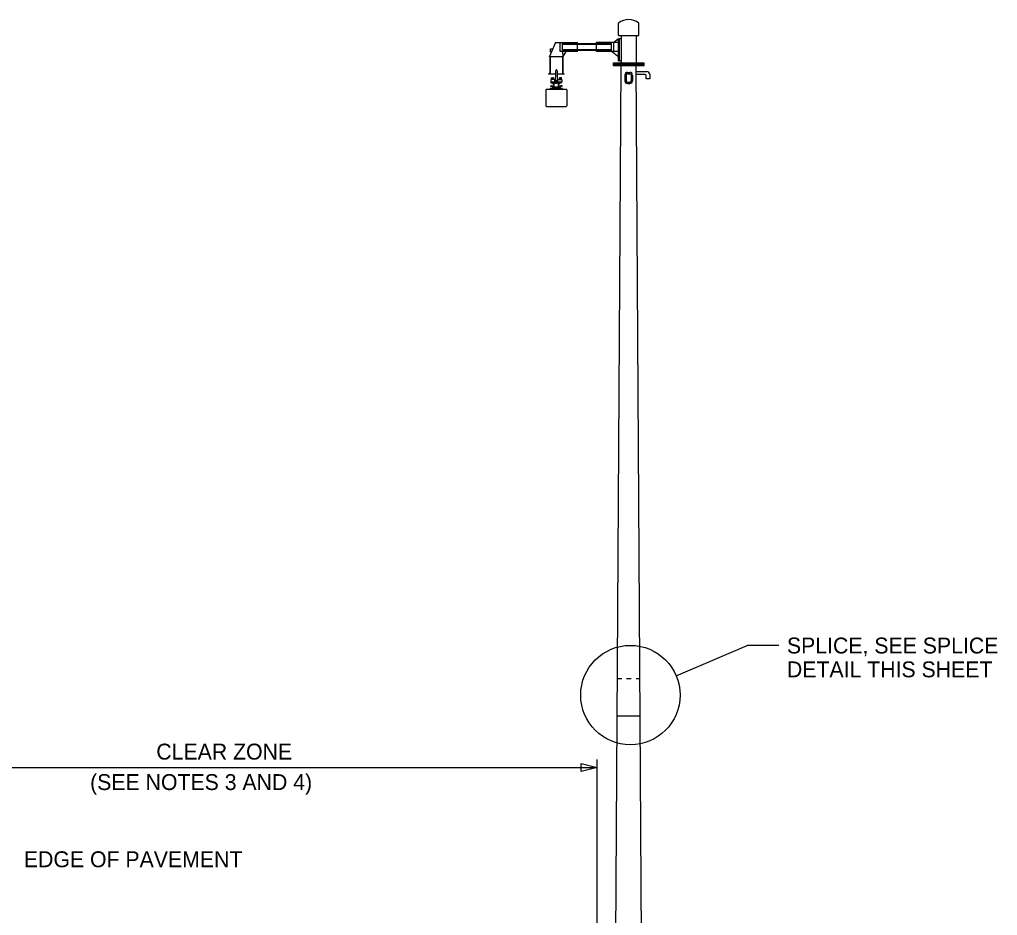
# Model space of a CAD drawing. Extents: x 1299104.8 to 1299141.6, y 239639.8 to 239661.8.
# Drawn here: x 1299111.4 to 1299118.78, y 239647.52 to 239654.28 of the extents above; entities that cross this region are included whole.
import ezdxf

# ---------------------------------------------------------------- set-up
doc = ezdxf.new("R2010")
doc.units = 0
for name, color, linetype in [('0-STEEL POLE', 7, 'Continuous'), ('DIM TXT', 7, 'Continuous'), ('Level 3', 7, 'Continuous'), ('Level 8', 7, 'Continuous')]:
    doc.layers.add(name, color=color, linetype=linetype)

# ---------------------------------------------------------------- blocks, each defined once
blk = doc.blocks.new('_U22')
at = {"layer": '0-STEEL POLE'}
for p, q in [((-0.054, 0.042), (-0.054, -0.042)), ((-0.035, 0.042), (-0.035, -0.042)), ((-0.018, 0.078), (0.018, 0.078)), ((-0.018, 0.06), (0.018, 0.06)), ((0.036, 0.042), (0.036, -0.042)), ((0.054, 0.041), (0.054, -0.042)), ((-0.018, -0.06), (0.018, -0.06)), ((-0.018, -0.077), (0.018, -0.077))]:
    blk.add_line(p, q, dxfattribs=at)
for centre, radius, start, end in [((-0.018, 0.042), 0.0357, 89.9999, 179.9999), ((-0.018, 0.042), 0.0179, 89.9999, 179.9999), ((0.018, 0.042), 0.0357, 359.9999, 89.9999), ((0.018, 0.042), 0.0179, 359.9999, 89.9999), ((-0.018, -0.042), 0.0357, 179.9999, 269.9999), ((-0.018, -0.042), 0.0179, 179.9999, 269.9999), ((0.018, -0.042), 0.0179, 269.9999, 359.9999), ((0.018, -0.042), 0.0357, 269.9999, 359.9999)]:
    blk.add_arc(centre, radius, start, end, dxfattribs=at)

msp = doc.modelspace()

# ---------------------------------------------------------------- linework, layer by layer
at = {"layer": 'Level 3'}
for p, q in [((1299115.9199, 239654.1559), (1299115.9199, 239654.2498)), ((1299116.0735, 239654.1559), (1299116.0735, 239654.2498)), ((1299115.4444, 239654.1034), (1299115.398, 239653.9986)), ((1299115.4444, 239654.1034), (1299115.6104, 239654.1034)), ((1299115.4805, 239654.036), (1299115.4805, 239654.1034)), ((1299115.4971, 239654.036), (1299115.4971, 239654.1034)), ((1299115.4971, 239654.095), (1299115.6104, 239654.095)), ((1299115.6104, 239654.095), (1299115.6104, 239654.1034)), ((1299115.6104, 239654.036), (1299115.6104, 239654.095)), ((1299115.6104, 239654.095), (1299115.7528, 239654.095)), ((1299115.9189, 239654.1034), (1299115.7528, 239654.1034)), ((1299115.7528, 239654.036), (1299115.7528, 239654.1034)), ((1299115.7528, 239654.095), (1299115.8661, 239654.095)), ((1299115.8661, 239654.036), (1299115.8661, 239654.1034)), ((1299115.9189, 239654.1314), (1299115.8845, 239654.1034)), ((1299115.8845, 239654.036), (1299115.8845, 239654.1034)), ((1299115.9189, 239653.9654), (1299115.9189, 239654.1314)), ((1299115.9189, 239654.1314), (1299115.9276, 239654.1314)), ((1299115.9199, 239654.1559), (1299116.0735, 239654.1559)), ((1299115.9276, 239653.9654), (1299115.9276, 239654.1314)), ((1299115.9399, 239654.1314), (1299115.9276, 239654.1314)), ((1299115.9399, 239654.1559), (1299115.9399, 239653.9498)), ((1299116.0535, 239654.1559), (1299116.0535, 239653.9498)), ((1299115.4063, 239654.0332), (1299115.4063, 239654.0563)), ((1299115.4063, 239654.0332), (1299115.4133, 239654.0332)), ((1299115.4065, 239654.0562), (1299115.4235, 239654.0562)), ((1299115.6104, 239654.036), (1299115.4805, 239654.036)), ((1299115.4971, 239654.0904), (1299115.6104, 239654.0904)), ((1299115.4971, 239654.0508), (1299115.6104, 239654.0508)), ((1299115.4971, 239654.0462), (1299115.6104, 239654.0462)), ((1299115.5024, 239653.9986), (1299115.5, 239654.036)), ((1299115.5024, 239653.9986), (1299115.5248, 239654.036)), ((1299115.5259, 239654.0462), (1299115.5361, 239654.0462)), ((1299115.5822, 239654.0462), (1299115.5923, 239654.0462)), ((1299115.6104, 239654.0904), (1299115.7528, 239654.0904)), ((1299115.6104, 239654.0508), (1299115.7528, 239654.0508)), ((1299115.6104, 239654.0462), (1299115.7528, 239654.0462)), ((1299115.7528, 239654.0904), (1299115.8661, 239654.0904)), ((1299115.7528, 239654.0508), (1299115.8661, 239654.0508)), ((1299115.7528, 239654.0462), (1299115.8661, 239654.0462)), ((1299115.8661, 239654.036), (1299115.7528, 239654.036)), ((1299115.7709, 239654.036), (1299115.7528, 239654.036)), ((1299115.7709, 239654.0462), (1299115.7811, 239654.0462)), ((1299115.8272, 239654.0462), (1299115.8373, 239654.0462)), ((1299115.9189, 239654.036), (1299115.8373, 239654.036)), ((1299115.9189, 239653.9945), (1299115.8661, 239654.036)), ((1299115.398, 239653.9986), (1299115.5024, 239653.9986)), ((1299115.398, 239653.9945), (1299115.398, 239653.9986)), ((1299115.5024, 239653.9945), (1299115.398, 239653.9945)), ((1299115.398, 239653.9945), (1299115.3998, 239653.9945)), ((1299115.4035, 239653.9966), (1299115.3998, 239653.9966)), ((1299115.3998, 239653.9945), (1299115.3998, 239653.9966)), ((1299115.402, 239653.9945), (1299115.402, 239653.8755)), ((1299115.4984, 239653.9945), (1299115.402, 239653.9945)), ((1299115.4028, 239653.9945), (1299115.4028, 239653.8745)), ((1299115.4035, 239653.9945), (1299115.4035, 239653.9966)), ((1299115.4969, 239653.9966), (1299115.5006, 239653.9966)), ((1299115.4969, 239653.9945), (1299115.4969, 239653.9966)), ((1299115.4976, 239653.9945), (1299115.4976, 239653.8745)), ((1299115.4984, 239653.9945), (1299115.4984, 239653.8755)), ((1299115.5006, 239653.9945), (1299115.5006, 239653.9966)), ((1299115.5006, 239653.9945), (1299115.5024, 239653.9945)), ((1299115.5024, 239653.9945), (1299115.5024, 239653.9986)), ((1299115.9189, 239653.9654), (1299115.9276, 239653.9654)), ((1299115.9399, 239653.9654), (1299115.9276, 239653.9654)), ((1299115.4439, 239653.8819), (1299115.4424, 239653.8032)), ((1299115.4468, 239653.8959), (1299115.4439, 239653.8819)), ((1299115.4477, 239653.8967), (1299115.4527, 239653.8967)), ((1299115.4536, 239653.8959), (1299115.4565, 239653.8819)), ((1299115.4565, 239653.8819), (1299115.4575, 239653.8032)), ((1299115.883, 239644.3884), (1299115.9399, 239653.9384)), ((1299116.1104, 239644.3884), (1299116.0535, 239653.9384)), ((1299115.3909, 239653.8663), (1299115.3909, 239653.8653)), ((1299115.4436, 239653.8653), (1299115.3909, 239653.8653)), ((1299115.4081, 239653.8233), (1299115.4081, 239653.8051)), ((1299115.4368, 239653.8251), (1299115.4099, 239653.8251)), ((1299115.4099, 239653.8033), (1299115.4203, 239653.8032)), ((1299115.4124, 239653.7972), (1299115.4124, 239653.8032)), ((1299115.4166, 239653.8032), (1299115.4124, 239653.8032)), ((1299115.4132, 239653.8251), (1299115.4132, 239653.827)), ((1299115.4141, 239653.8279), (1299115.4141, 239653.8363)), ((1299115.416, 239653.8279), (1299115.4141, 239653.8279)), ((1299115.416, 239653.8279), (1299115.416, 239653.8363)), ((1299115.4169, 239653.8251), (1299115.4169, 239653.827)), ((1299115.4175, 239653.8251), (1299115.4175, 239653.827)), ((1299115.4575, 239653.8032), (1299115.4175, 239653.8032)), ((1299115.4185, 239653.8279), (1299115.4185, 239653.8363)), ((1299115.4203, 239653.8279), (1299115.4185, 239653.8279)), ((1299115.4203, 239653.8279), (1299115.4203, 239653.8363)), ((1299115.4212, 239653.8251), (1299115.4212, 239653.827)), ((1299115.4212, 239653.8032), (1299115.4386, 239653.8032)), ((1299115.422, 239653.8251), (1299115.422, 239653.827)), ((1299115.4229, 239653.8279), (1299115.4229, 239653.8363)), ((1299115.4248, 239653.8279), (1299115.4229, 239653.8279)), ((1299115.4248, 239653.8279), (1299115.4248, 239653.8363)), ((1299115.4257, 239653.8251), (1299115.4257, 239653.827)), ((1299115.426, 239653.8251), (1299115.426, 239653.827)), ((1299115.4269, 239653.8279), (1299115.4269, 239653.8363)), ((1299115.4288, 239653.8279), (1299115.4269, 239653.8279)), ((1299115.4288, 239653.8279), (1299115.4288, 239653.8363)), ((1299115.4291, 239653.8032), (1299115.4291, 239653.7972)), ((1299115.4297, 239653.8251), (1299115.4297, 239653.827)), ((1299115.4386, 239653.8032), (1299115.4386, 239653.8233)), ((1299115.4417, 239653.7987), (1299115.4417, 239653.8021)), ((1299115.4456, 239653.7987), (1299115.4456, 239653.8021)), ((1299115.4479, 239653.7904), (1299115.4479, 239653.8183)), ((1299115.4525, 239653.7904), (1299115.4525, 239653.8183)), ((1299115.4548, 239653.7987), (1299115.4548, 239653.8021)), ((1299115.5087, 239653.8653), (1299115.4565, 239653.8653)), ((1299115.488, 239653.8032), (1299115.4575, 239653.8032)), ((1299115.4587, 239653.7987), (1299115.4587, 239653.8021)), ((1299115.461, 239653.8032), (1299115.461, 239653.8233)), ((1299115.4897, 239653.8033), (1299115.461, 239653.8032)), ((1299115.4628, 239653.8251), (1299115.4653, 239653.8251)), ((1299115.4653, 239653.8251), (1299115.4897, 239653.8251)), ((1299115.4714, 239653.8032), (1299115.4714, 239653.7972)), ((1299115.4732, 239653.8251), (1299115.4732, 239653.827)), ((1299115.4742, 239653.8279), (1299115.4742, 239653.8363)), ((1299115.4742, 239653.8279), (1299115.476, 239653.8279)), ((1299115.476, 239653.8279), (1299115.476, 239653.8363)), ((1299115.4769, 239653.8251), (1299115.4769, 239653.827)), ((1299115.4772, 239653.8251), (1299115.4772, 239653.827)), ((1299115.4781, 239653.8279), (1299115.4781, 239653.8363)), ((1299115.4781, 239653.8279), (1299115.48, 239653.8279)), ((1299115.48, 239653.8279), (1299115.48, 239653.8363)), ((1299115.4809, 239653.8251), (1299115.4809, 239653.827)), ((1299115.4817, 239653.8251), (1299115.4817, 239653.827)), ((1299115.4826, 239653.8279), (1299115.4826, 239653.8363)), ((1299115.4826, 239653.8279), (1299115.4845, 239653.8279)), ((1299115.4845, 239653.8279), (1299115.4845, 239653.8363)), ((1299115.4854, 239653.8251), (1299115.4854, 239653.827)), ((1299115.486, 239653.8251), (1299115.486, 239653.827)), ((1299115.487, 239653.8279), (1299115.487, 239653.8363)), ((1299115.487, 239653.8279), (1299115.4888, 239653.8279)), ((1299115.488, 239653.7972), (1299115.488, 239653.8032)), ((1299115.4888, 239653.8279), (1299115.4888, 239653.8363)), ((1299115.4897, 239653.8251), (1299115.4897, 239653.827)), ((1299115.4915, 239653.8233), (1299115.4915, 239653.8051)), ((1299115.5087, 239653.8663), (1299115.5087, 239653.8653)), ((1299115.372, 239653.7471), (1299115.372, 239653.6253)), ((1299115.3757, 239653.7508), (1299115.5252, 239653.7508)), ((1299115.4064, 239653.7774), (1299115.4055, 239653.7765)), ((1299115.4055, 239653.7765), (1299115.4067, 239653.7752)), ((1299115.4064, 239653.7774), (1299115.433, 239653.7774)), ((1299115.4064, 239653.7774), (1299115.4073, 239653.7765)), ((1299115.4066, 239653.7577), (1299115.4943, 239653.7577)), ((1299115.4066, 239653.7508), (1299115.4066, 239653.7577)), ((1299115.4081, 239653.7746), (1299115.4144, 239653.7746)), ((1299115.4085, 239653.7746), (1299115.4085, 239653.7759)), ((1299115.4087, 239653.7758), (1299115.415, 239653.7758)), ((1299115.4113, 239653.7746), (1299115.4113, 239653.7758)), ((1299115.4591, 239653.7972), (1299115.4124, 239653.7972)), ((1299115.4252, 239653.7669), (1299115.4159, 239653.7577)), ((1299115.4172, 239653.7733), (1299115.4219, 239653.7681)), ((1299115.4178, 239653.7746), (1299115.4225, 239653.7694)), ((1299115.4246, 239653.7669), (1299115.433, 239653.7669)), ((1299115.433, 239653.7839), (1299115.4247, 239653.7972)), ((1299115.4252, 239653.7682), (1299115.433, 239653.7682)), ((1299115.4757, 239653.7669), (1299115.4252, 239653.7669)), ((1299115.4252, 239653.7577), (1299115.4252, 239653.7669)), ((1299115.4277, 239653.7669), (1299115.4277, 239653.7682)), ((1299115.433, 239653.7682), (1299115.433, 239653.7972)), ((1299115.433, 239653.7669), (1299115.433, 239653.7682)), ((1299115.4431, 239653.7669), (1299115.4573, 239653.7669)), ((1299115.4433, 239653.7669), (1299115.4433, 239653.7682)), ((1299115.4493, 239653.7669), (1299115.4493, 239653.7682)), ((1299115.4511, 239653.7669), (1299115.4511, 239653.7682)), ((1299115.4571, 239653.7669), (1299115.4571, 239653.7682)), ((1299115.488, 239653.7972), (1299115.4591, 239653.7972)), ((1299115.4675, 239653.7682), (1299115.4675, 239653.7972)), ((1299115.4675, 239653.7839), (1299115.4758, 239653.7972)), ((1299115.4675, 239653.7774), (1299115.494, 239653.7774)), ((1299115.4675, 239653.7669), (1299115.4675, 239653.7682)), ((1299115.4675, 239653.7682), (1299115.4752, 239653.7682)), ((1299115.4675, 239653.7669), (1299115.4758, 239653.7669)), ((1299115.4727, 239653.7669), (1299115.4727, 239653.7682)), ((1299115.4757, 239653.7577), (1299115.4757, 239653.7669)), ((1299115.4757, 239653.7669), (1299115.485, 239653.7577)), ((1299115.4827, 239653.7746), (1299115.478, 239653.7694)), ((1299115.4832, 239653.7733), (1299115.4785, 239653.7681)), ((1299115.4918, 239653.7758), (1299115.4854, 239653.7758)), ((1299115.4923, 239653.7746), (1299115.486, 239653.7746)), ((1299115.4891, 239653.7746), (1299115.4891, 239653.7758)), ((1299115.4919, 239653.7746), (1299115.4919, 239653.7759)), ((1299115.494, 239653.7774), (1299115.4931, 239653.7765)), ((1299115.495, 239653.7765), (1299115.4937, 239653.7752)), ((1299115.494, 239653.7774), (1299115.495, 239653.7765)), ((1299115.4943, 239653.7508), (1299115.4943, 239653.7577)), ((1299115.5289, 239653.7471), (1299115.5289, 239653.6253)), ((1299115.3757, 239653.6216), (1299115.5252, 239653.6216)), ((1299115.9123, 239649.304), (1299115.946, 239649.304)), ((1299115.9795, 239649.304), (1299116.0152, 239649.304)), ((1299116.053, 239649.304), (1299116.0811, 239649.304)), ((1299115.9106, 239649.0228), (1299116.0828, 239649.0228))]:
    msp.add_line(p, q, dxfattribs=at)
for points in [[(1299115.883, 239653.9498), (1299116.1104, 239653.9498), (1299116.1104, 239653.9384), (1299115.883, 239653.9384)], [(1299115.883, 239653.9384), (1299116.1104, 239653.9384), (1299116.1104, 239653.9271), (1299115.883, 239653.9271)]]:
    msp.add_lwpolyline(points, close=True, dxfattribs=at)
for points in [[(1299116.0539, 239653.8843), (1299116.1332, 239653.8843)], [(1299116.1218, 239653.8611), (1299116.054, 239653.8611)], [(1299116.1558, 239653.8617), (1299116.1558, 239653.8288), (1299116.1293, 239653.8288), (1299116.1293, 239653.8536)]]:
    msp.add_lwpolyline(points, dxfattribs=at)
for centre, radius, start, end in [((1299115.9967, 239654.153), 0.1236, 51.5919, 128.4081), ((1299115.392, 239653.8762), 0.00999, 265.76361, 355.76361), ((1299115.3925, 239653.8757), 0.0104, 295.12935, 353.60131), ((1299115.4477, 239653.8957), 0.000923, 90, 168.17452), ((1299115.4527, 239653.8957), 0.000923, 11.82548, 90), ((1299115.5078, 239653.8757), 0.0103, 186.13054, 245.45851), ((1299115.5083, 239653.8762), 0.00994, 184.10961, 269.76399), ((1299116.1332, 239653.8617), 0.0226, 359.99994, 89.99994), ((1299115.4099, 239653.8233), 0.00185, 90, 180), ((1299115.4099, 239653.8051), 0.00185, 180, 269.7176), ((1299115.4141, 239653.827), 0.000923, 90, 180), ((1299115.415, 239653.8363), 0.000923, 0, 180), ((1299115.416, 239653.827), 0.000923, 0, 90), ((1299115.4185, 239653.827), 0.000923, 90, 180), ((1299115.4194, 239653.8363), 0.000923, 0, 180), ((1299115.4203, 239653.827), 0.000923, 0, 90), ((1299115.4229, 239653.827), 0.000923, 90, 180), ((1299115.4239, 239653.8363), 0.000923, 0, 180), ((1299115.4248, 239653.827), 0.000923, 0, 90), ((1299115.4269, 239653.827), 0.000923, 90, 180), ((1299115.4278, 239653.8363), 0.000923, 0, 180), ((1299115.4288, 239653.827), 0.000923, 0, 90), ((1299115.4368, 239653.8233), 0.00185, 0, 90), ((1299115.4628, 239653.8233), 0.00185, 90, 180), ((1299115.4742, 239653.827), 0.000923, 90, 180), ((1299115.4751, 239653.8363), 0.000923, 0, 180), ((1299115.476, 239653.827), 0.000923, 0, 90), ((1299115.4781, 239653.827), 0.000923, 90, 180), ((1299115.479, 239653.8363), 0.000923, 0, 180), ((1299115.48, 239653.827), 0.000923, 0, 90), ((1299115.4826, 239653.827), 0.000923, 90, 180), ((1299115.4835, 239653.8363), 0.000923, 0, 180), ((1299115.4845, 239653.827), 0.000923, 0, 90), ((1299115.487, 239653.827), 0.000923, 90, 180), ((1299115.4879, 239653.8363), 0.000923, 0, 180), ((1299115.4888, 239653.827), 0.000923, 0, 90), ((1299115.4897, 239653.8233), 0.00185, 0, 90), ((1299115.4897, 239653.8051), 0.00185, 270.2824, 0), ((1299116.1218, 239653.8536), 0.00753, 359.99994, 89.99994), ((1299115.3757, 239653.7471), 0.00369, 90, 180), ((1299115.4081, 239653.7764), 0.00185, 222.08916, 270), ((1299115.4087, 239653.7777), 0.00185, 222.08916, 270), ((1299115.4144, 239653.7709), 0.00369, 42.10142, 90), ((1299115.415, 239653.7722), 0.00369, 42.10142, 90), ((1299115.4246, 239653.7706), 0.00369, 222.10142, 270), ((1299115.4252, 239653.7719), 0.00369, 222.10142, 270), ((1299115.4752, 239653.7719), 0.00369, 270, 317.89858), ((1299115.4758, 239653.7706), 0.00369, 270, 317.89858), ((1299115.4854, 239653.7722), 0.00369, 90, 137.89858), ((1299115.486, 239653.7709), 0.00369, 90, 137.89858), ((1299115.4918, 239653.7777), 0.00185, 270, 317.91084), ((1299115.4923, 239653.7764), 0.00185, 270, 317.91084), ((1299115.5252, 239653.7471), 0.00369, 0, 90), ((1299115.3757, 239653.6253), 0.00369, 180, 270), ((1299115.5252, 239653.6253), 0.00369, 270, 0)]:
    msp.add_arc(centre, radius, start, end, dxfattribs=at)
at = {"layer": 'Level 8'}
for p, q in [((1299116.3545, 239649.3251), (1299116.8915, 239649.5528)), ((1299117.1315, 239649.5528), (1299116.8915, 239649.5528)), ((1299110.4046, 239648.6321), (1299115.758, 239648.6321)), ((1299115.758, 239644.394), (1299115.758, 239648.6921))]:
    msp.add_line(p, q, dxfattribs=at)
msp.add_lwpolyline([(1299115.638, 239648.6621), (1299115.758, 239648.6321), (1299115.638, 239648.6021)], close=True, dxfattribs=at)
msp.add_circle((1299116.0093, 239649.1787), 0.375, dxfattribs=at)

# ---------------------------------------------------------------- block references
at = {"layer": 'Level 3', "xscale": 0.5371235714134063, "yscale": 0.5371235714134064, "rotation": 0.00013320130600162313}
msp.add_blockref('_U22', (1299115.9965, 239653.8357), dxfattribs=at)

# ---------------------------------------------------------------- texts
at = {"layer": 'DIM TXT'}
for s, p in [('SPLICE, SEE SPLICE', (1299117.1915, 239649.4928)), ('DETAIL THIS SHEET', (1299117.1915, 239649.3128)), ('CLEAR ZONE', (1299112.43, 239648.6921)), ('(SEE NOTES 3 AND 4)', (1299111.9301, 239648.4621)), ('EDGE OF PAVEMENT', (1299111.4301, 239647.8796))]:
    msp.add_text(s, height=0.12, dxfattribs=at).set_placement(p)

doc.saveas('drawing.dxf')
